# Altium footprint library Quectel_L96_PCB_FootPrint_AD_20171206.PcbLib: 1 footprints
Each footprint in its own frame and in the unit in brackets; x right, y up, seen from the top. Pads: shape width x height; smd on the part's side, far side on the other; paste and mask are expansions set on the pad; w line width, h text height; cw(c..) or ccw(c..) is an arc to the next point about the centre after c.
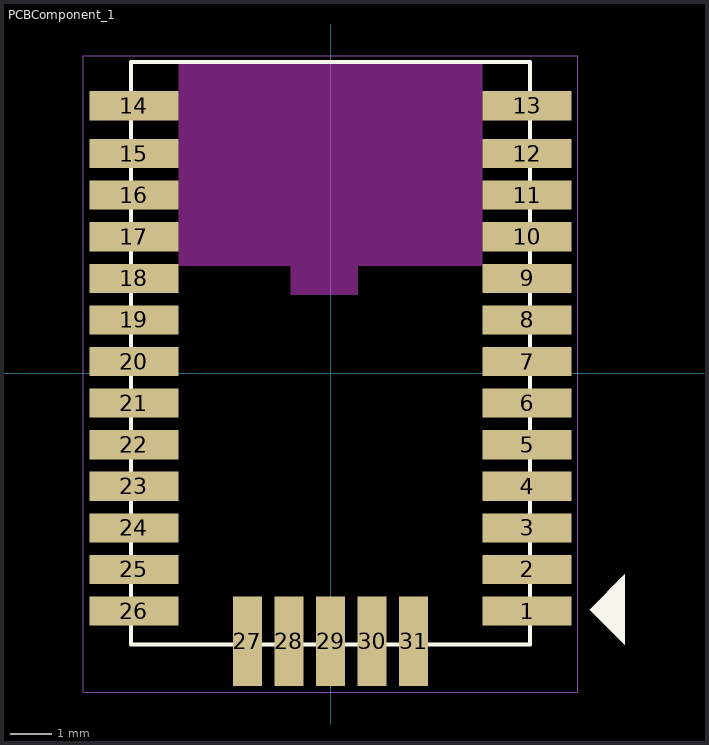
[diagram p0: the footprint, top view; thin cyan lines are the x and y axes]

## PCBComponent_1 [mm]
pads (31):
  rect 2.15x0.7 smd mask+0.05: 1(4.725,-5.713) 2(4.725,-4.713) 3(4.725,-3.712) 4(4.725,-2.713) 5(4.725,-1.713) 6(4.725,-0.713) 7(4.725,0.288) 8(4.725,1.288) 9(4.725,2.287) 10(4.725,3.287) 11(4.725,4.287) 12(4.725,5.288) 13(4.725,6.438) 14(-4.725,6.438) 15(-4.725,5.288) 16(-4.725,4.287) 17(-4.725,3.287) 18(-4.725,2.287) 19(-4.725,1.288) 20(-4.725,0.288) 21(-4.725,-0.713) 22(-4.725,-1.713) 23(-4.725,-2.713) 24(-4.725,-3.712) 25(-4.725,-4.713) 26(-4.725,-5.713)
  rect 0.7x2.15 smd mask+0.05: 27(-2,-6.438) 28(-1,-6.438) 29(0,-6.438) 30(1,-6.438) 31(2,-6.438)
Top Overlay:
  region: 7.08,-4.832 6.235,-5.677 7.08,-6.523
  lines w0.1: -4.8,-6.513 -4.8,7.488 4.8,7.488 4.8,-6.513 4.46,-6.513 -4.8,-6.513
Keep-Out Layer:
  region: -3.65,7.488 3.65,7.488 3.65,2.588 0.65,2.588 0.65,1.887 -0.95,1.887 -0.95,2.588 -3.65,2.588
Mechanical 1:
  lines w0.01: -5.95,-7.662 -5.95,7.638 5.95,7.638 5.95,-7.662 -5.95,-7.662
